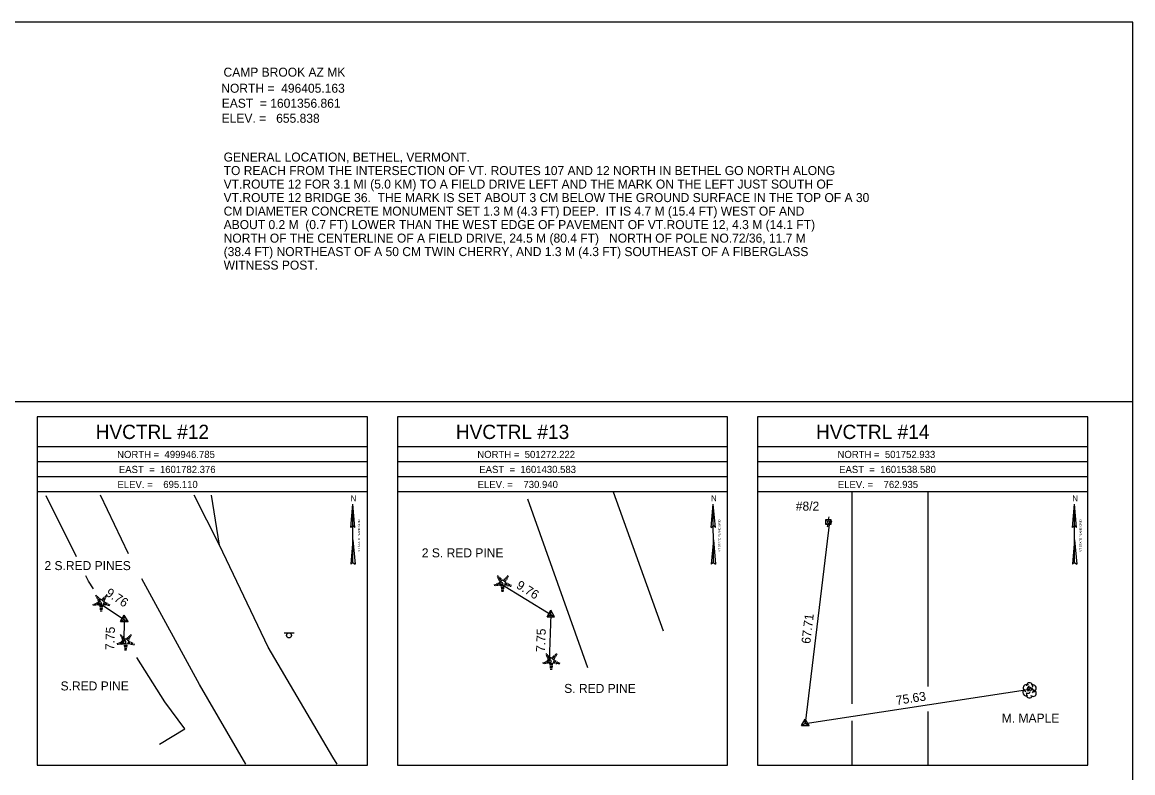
# Model space of a CAD drawing. Extents: x 1598730 to 1599370, y 501440 to 502728.
# Drawn here: x 1598999.5 to 1599369.5, y 502042.9 to 502293 of the extents above; entities that cross this region are included whole.
import ezdxf

# ---------------------------------------------------------------- set-up
doc = ezdxf.new("R2010")
doc.units = 0
for name, color, linetype in [('CBP', 7, 'Continuous'), ('CPSM', 7, 'Continuous'), ('Default', 7, 'Continuous'), ('L_C', 7, 'Continuous'), ('LAWA', 7, 'Continuous'), ('LTC', 7, 'Continuous'), ('LTD', 7, 'Continuous'), ('NBL1', 7, 'Continuous'), ('NBL2', 7, 'Continuous'), ('NNA_P', 7, 'Continuous'), ('PET', 7, 'Continuous'), ('RDG', 7, 'Continuous'), ('SSGN', 7, 'Continuous'), ('U_C', 7, 'Continuous'), ('UP', 7, 'Continuous')]:
    doc.layers.add(name, color=color, linetype=linetype)

msp = doc.modelspace()

# ---------------------------------------------------------------- linework, layer by layer
at = {"layer": 'CBP'}
for centre, radius in [((1599268.48, 502126.59), 0.625), ((1599268.48, 502126.59), 0.0833), ((1599159.02, 502105.88), 0.625), ((1599159.02, 502105.88), 0.0833), ((1599025.29, 502099.39), 0.625), ((1599025.29, 502099.39), 0.0833), ((1599033.34, 502086.52), 0.625), ((1599033.34, 502086.52), 0.0833), ((1599175.12, 502080.15), 0.625), ((1599175.12, 502080.15), 0.0833), ((1599335.18, 502070.79), 0.625), ((1599335.18, 502070.79), 0.0833)]:
    msp.add_circle(centre, radius, dxfattribs=at)
at = {"layer": 'CPSM'}
for p, q in [((1599032.29, 502093.33), (1599033.54, 502095.5)), ((1599034.79, 502093.33), (1599033.54, 502095.5)), ((1599033.54, 502094.05), (1599033.54, 502095.5)), ((1599174.39, 502094.93), (1599175.64, 502097.1)), ((1599174.39, 502094.93), (1599175.64, 502095.65)), ((1599174.39, 502094.93), (1599176.89, 502094.93)), ((1599176.89, 502094.93), (1599175.64, 502097.1)), ((1599175.64, 502095.65), (1599175.64, 502097.1)), ((1599175.64, 502095.65), (1599175.64, 502095.65)), ((1599175.64, 502095.65), (1599176.89, 502094.93)), ((1599032.29, 502093.33), (1599033.54, 502094.05)), ((1599032.29, 502093.33), (1599034.79, 502093.33)), ((1599033.54, 502094.05), (1599033.54, 502094.05)), ((1599033.54, 502094.05), (1599034.79, 502093.33)), ((1599259.18, 502058.64), (1599260.43, 502060.8)), ((1599259.18, 502058.64), (1599260.43, 502059.36)), ((1599259.18, 502058.64), (1599261.68, 502058.64)), ((1599261.68, 502058.64), (1599260.43, 502060.8)), ((1599260.43, 502059.36), (1599260.43, 502060.8)), ((1599260.43, 502059.36), (1599260.43, 502059.36)), ((1599260.43, 502059.36), (1599261.68, 502058.64))]:
    msp.add_line(p, q, dxfattribs=at)
at = {"layer": 'Default'}
for p, q in [((1599268.48, 502126.59), (1599260.43, 502059.36)), ((1599159.02, 502105.88), (1599175.64, 502095.65)), ((1599025.29, 502099.39), (1599033.54, 502094.05)), ((1599175.64, 502095.65), (1599175.12, 502080.15)), ((1599033.54, 502094.05), (1599033.34, 502086.52)), ((1599260.43, 502059.36), (1599335.18, 502070.79))]:
    msp.add_line(p, q, dxfattribs=at)
at = {"layer": 'LAWA'}
for points in [[(1599017.62, 502114.88), (1599007.56, 502135.25)], [(1599023.27, 502104.18), (1599021.6, 502106.82), (1599020.73, 502108.58)], [(1599045.31, 502052.43), (1599053.66, 502057.56), (1599047.04, 502066.58), (1599037.69, 502081.36)]]:
    msp.add_lwpolyline(points, dxfattribs=at)
at = {"layer": 'LTC'}
for p, q in [((1599156.75, 502105.65), (1599156.9, 502105.18)), ((1599157.21, 502105.87), (1599157.42, 502105.22)), ((1599157.66, 502106.08), (1599157.93, 502105.25)), ((1599157.72, 502108.37), (1599158.07, 502108.63)), ((1599157.93, 502107.91), (1599158.46, 502108.29)), ((1599158.12, 502106.3), (1599158.45, 502105.28)), ((1599158.14, 502107.44), (1599158.84, 502107.95)), ((1599158.35, 502106.97), (1599159.23, 502107.61)), ((1599158.57, 502106.52), (1599159.58, 502107.25)), ((1599158.57, 502106.52), (1599158.96, 502105.33)), ((1599159.58, 502107.25), (1599160.58, 502106.53)), ((1599160, 502107.57), (1599160.81, 502106.98)), ((1599160.58, 502106.53), (1599160.19, 502105.33)), ((1599160.38, 502107.91), (1599161.05, 502107.42)), ((1599161.02, 502106.26), (1599160.68, 502105.22)), ((1599160.75, 502108.26), (1599161.3, 502107.86)), ((1599161.12, 502108.61), (1599161.54, 502108.31)), ((1599161.46, 502106.01), (1599161.18, 502105.12)), ((1599161.91, 502105.76), (1599161.67, 502105.03)), ((1599162.35, 502105.51), (1599162.17, 502104.93)), ((1599023.99, 502101.88), (1599024.34, 502102.13)), ((1599024.2, 502101.41), (1599024.73, 502101.8)), ((1599027.02, 502101.77), (1599027.56, 502101.37)), ((1599027.39, 502102.12), (1599027.81, 502101.81)), ((1599160.19, 502105.33), (1599158.96, 502105.33)), ((1599160.15, 502104.83), (1599159.01, 502104.83)), ((1599160.07, 502104.33), (1599159.08, 502104.33)), ((1599159.98, 502103.83), (1599159.15, 502103.83)), ((1599159.9, 502103.33), (1599159.23, 502103.33)), ((1599023.02, 502099.16), (1599023.17, 502098.69)), ((1599023.48, 502099.37), (1599023.69, 502098.72)), ((1599023.93, 502099.59), (1599024.2, 502098.75)), ((1599024.39, 502099.81), (1599024.72, 502098.79)), ((1599024.41, 502100.95), (1599025.11, 502101.46)), ((1599024.62, 502100.48), (1599025.5, 502101.12)), ((1599024.84, 502100.03), (1599025.85, 502100.76)), ((1599024.84, 502100.03), (1599025.23, 502098.83)), ((1599026.46, 502098.83), (1599025.23, 502098.83)), ((1599026.42, 502098.33), (1599025.28, 502098.33)), ((1599025.85, 502100.76), (1599026.85, 502100.03)), ((1599026.27, 502101.07), (1599027.08, 502100.48)), ((1599026.85, 502100.03), (1599026.46, 502098.83)), ((1599026.64, 502101.42), (1599027.32, 502100.93)), ((1599027.29, 502099.76), (1599026.95, 502098.72)), ((1599027.73, 502099.51), (1599027.44, 502098.63)), ((1599028.18, 502099.26), (1599027.94, 502098.53)), ((1599028.62, 502099.01), (1599028.43, 502098.44)), ((1599026.34, 502097.83), (1599025.35, 502097.83)), ((1599026.25, 502097.33), (1599025.42, 502097.33)), ((1599026.17, 502096.83), (1599025.49, 502096.83)), ((1599032.14, 502088.79), (1599032.5, 502089.05)), ((1599032.35, 502088.33), (1599032.88, 502088.71)), ((1599032.56, 502087.86), (1599033.27, 502088.37)), ((1599032.77, 502087.4), (1599033.65, 502088.03)), ((1599033, 502086.94), (1599034.01, 502087.68)), ((1599033, 502086.94), (1599033.39, 502085.75)), ((1599034.01, 502087.68), (1599035.01, 502086.95)), ((1599034.43, 502087.99), (1599035.24, 502087.4)), ((1599035.01, 502086.95), (1599034.62, 502085.75)), ((1599034.8, 502088.34), (1599035.48, 502087.84)), ((1599035.17, 502088.69), (1599035.72, 502088.29)), ((1599035.54, 502089.03), (1599035.96, 502088.73)), ((1599031.18, 502086.07), (1599031.33, 502085.6)), ((1599031.63, 502086.29), (1599031.84, 502085.64)), ((1599032.09, 502086.51), (1599032.36, 502085.67)), ((1599032.54, 502086.72), (1599032.87, 502085.7)), ((1599034.62, 502085.75), (1599033.39, 502085.75)), ((1599034.58, 502085.25), (1599033.43, 502085.25)), ((1599034.49, 502084.75), (1599033.51, 502084.75)), ((1599034.41, 502084.25), (1599033.58, 502084.25)), ((1599034.33, 502083.75), (1599033.65, 502083.75)), ((1599035.44, 502086.68), (1599035.11, 502085.64)), ((1599035.89, 502086.43), (1599035.6, 502085.54)), ((1599036.33, 502086.18), (1599036.1, 502085.45)), ((1599036.78, 502085.93), (1599036.59, 502085.35)), ((1599172.96, 502079.7), (1599173.11, 502079.23)), ((1599173.41, 502079.92), (1599173.63, 502079.26)), ((1599173.87, 502080.13), (1599174.14, 502079.3)), ((1599173.93, 502082.42), (1599174.28, 502082.68)), ((1599174.14, 502081.95), (1599174.67, 502082.34)), ((1599174.33, 502080.35), (1599174.66, 502079.33)), ((1599174.35, 502081.49), (1599175.05, 502082)), ((1599174.56, 502081.02), (1599175.43, 502081.66)), ((1599174.78, 502080.57), (1599175.79, 502081.3)), ((1599174.78, 502080.57), (1599175.17, 502079.37)), ((1599175.79, 502081.3), (1599176.79, 502080.58)), ((1599176.21, 502081.62), (1599177.02, 502081.03)), ((1599176.79, 502080.58), (1599176.4, 502079.37)), ((1599176.58, 502081.96), (1599177.26, 502081.47)), ((1599177.23, 502080.31), (1599176.89, 502079.27)), ((1599176.95, 502082.31), (1599177.5, 502081.91)), ((1599177.32, 502082.66), (1599177.74, 502082.36)), ((1599177.67, 502080.06), (1599177.38, 502079.17)), ((1599178.12, 502079.81), (1599177.88, 502079.08)), ((1599178.56, 502079.56), (1599178.37, 502078.98)), ((1599176.4, 502079.37), (1599175.17, 502079.37)), ((1599176.36, 502078.87), (1599175.21, 502078.87)), ((1599176.28, 502078.37), (1599175.29, 502078.37)), ((1599176.19, 502077.87), (1599175.36, 502077.87)), ((1599176.11, 502077.37), (1599175.43, 502077.37))]:
    msp.add_line(p, q, dxfattribs=at)
at = {"layer": 'LTD'}
msp.add_line((1599335.12, 502070.44), (1599335.12, 502070.44), dxfattribs=at)
msp.add_line((1599335.12, 502070.44), (1599335.12, 502070.44), dxfattribs=at)
msp.add_arc((1599335.17, 502071.88), 1.05, 335.5272, 180.9563, dxfattribs=at)
for centre, major_axis, ratio, start_param, end_param in [((1599334.33, 502071.11), (1.21, -0.51), 0.895232, 1.570796, 4.712389), ((1599336.16, 502071.03), (-1.14, -0.48), 0.949671, 1.570796, 4.712389), ((1599334.04, 502069.74), (0.58, -1.04), 0.959034, 3.141593, 6.283185), ((1599335.12, 502068.94), (0.26, 1.06), 0.942809, 1.570796, 4.712389), ((1599334.66, 502069.69), (-0.625, -0.083), 0.423636, 0, 3.141593), ((1599334.91, 502070.9), (-0.208, -0.792), 0.645439, 3.141593, 6.283185), ((1599335.62, 502070.28), (-0.5, 0.667), 0.989748, 3.141593, 6.283185), ((1599336.12, 502069.61), (-1.09, 0.79), 0.841452, 1.570796, 4.712389)]:
    msp.add_ellipse(centre, major_axis=major_axis, ratio=ratio, start_param=start_param, end_param=end_param, dxfattribs=at)
at = {"layer": 'NBL1'}
msp.add_lwpolyline([(1598729.53, 501873.01), (1599369.53, 501873.01), (1599369.53, 502293.01), (1598729.53, 502293.01)], close=True, dxfattribs=at)
at = {"layer": 'NBL2'}
for p, q in [((1598729.53, 502166.68), (1599369.53, 502166.68)), ((1599114.53, 502151.51), (1599004.53, 502151.51)), ((1599234.53, 502151.51), (1599124.53, 502151.51)), ((1599354.53, 502151.51), (1599244.53, 502151.51)), ((1599114.53, 502146.51), (1599004.53, 502146.51)), ((1599234.53, 502146.51), (1599124.53, 502146.51)), ((1599354.53, 502146.51), (1599244.53, 502146.51)), ((1599114.53, 502141.51), (1599004.53, 502141.51)), ((1599234.53, 502141.51), (1599124.53, 502141.51)), ((1599354.53, 502141.51), (1599244.53, 502141.51)), ((1599114.53, 502136.51), (1599004.53, 502136.51)), ((1599234.53, 502136.51), (1599124.53, 502136.51)), ((1599354.53, 502136.51), (1599244.53, 502136.51))]:
    msp.add_line(p, q, dxfattribs=at)
for points in [[(1599004.53, 502045.51), (1599114.53, 502045.51), (1599114.53, 502161.51), (1599004.53, 502161.51)], [(1599124.53, 502045.51), (1599234.53, 502045.51), (1599234.53, 502161.51), (1599124.53, 502161.51)], [(1599244.53, 502045.51), (1599354.53, 502045.51), (1599354.53, 502161.51), (1599244.53, 502161.51)]]:
    msp.add_lwpolyline(points, close=True, dxfattribs=at)
at = {"layer": 'NNA_P'}
for p, q in [((1599109.01, 502124.61), (1599109.7, 502132.4)), ((1599109.71, 502113.03), (1599109.7, 502132.4)), ((1599110.4, 502124.61), (1599109.7, 502132.4)), ((1599229.09, 502124.61), (1599229.78, 502132.4)), ((1599229.79, 502113.03), (1599229.78, 502132.4)), ((1599230.48, 502124.61), (1599229.78, 502132.4)), ((1599349.43, 502124.61), (1599350.12, 502132.4)), ((1599350.13, 502113.03), (1599350.12, 502132.4)), ((1599350.82, 502124.61), (1599350.12, 502132.4)), ((1599109.01, 502124.61), (1599109.7, 502125.37)), ((1599110.4, 502124.61), (1599109.71, 502125.37)), ((1599229.09, 502124.61), (1599229.79, 502125.37)), ((1599230.48, 502124.61), (1599229.79, 502125.37)), ((1599349.43, 502124.61), (1599350.12, 502125.37)), ((1599350.82, 502124.61), (1599350.13, 502125.37)), ((1599109.71, 502120.55), (1599108.99, 502112.39)), ((1599109.71, 502120.55), (1599110.43, 502112.39)), ((1599229.79, 502120.55), (1599229.07, 502112.39)), ((1599229.79, 502120.55), (1599230.51, 502112.39)), ((1599350.13, 502120.55), (1599349.41, 502112.39)), ((1599350.13, 502120.55), (1599350.85, 502112.39)), ((1599109.71, 502113.03), (1599108.99, 502112.39)), ((1599109.71, 502113.03), (1599110.43, 502112.39)), ((1599229.79, 502113.03), (1599229.07, 502112.39)), ((1599229.79, 502113.03), (1599230.51, 502112.39)), ((1599350.13, 502113.03), (1599349.41, 502112.39)), ((1599350.13, 502113.03), (1599350.85, 502112.39))]:
    msp.add_line(p, q, dxfattribs=at)
at = {"layer": 'PET'}
for points in [[(1599034.98, 502115.83), (1599025.58, 502135.48)], [(1599104.48, 502045.81), (1599103.01, 502048.17), (1599081.45, 502084.79), (1599065.29, 502118.75), (1599056.78, 502135.48)], [(1599196.43, 502136.51), (1599213.07, 502090.21)], [(1599275.89, 502136.51), (1599275.89, 502065.89)], [(1599301.25, 502136.51), (1599301.25, 502071.71)], [(1599167.83, 502134.25), (1599187.82, 502077.96)], [(1599074.08, 502045.81), (1599058.64, 502072.38), (1599039.39, 502107.58)], [(1599301.25, 502063.3), (1599301.25, 502045.51)], [(1599275.89, 502060.22), (1599275.89, 502045.51)]]:
    msp.add_lwpolyline(points, dxfattribs=at)
at = {"layer": 'RDG'}
msp.add_lwpolyline([(1599065.29, 502118.75), (1599062.55, 502135.48)], dxfattribs=at)
at = {"layer": 'SSGN'}
for p, q in [((1599086.77, 502089.54), (1599090.11, 502089.54)), ((1599088.42, 502088.71), (1599088.42, 502088.71))]:
    msp.add_line(p, q, dxfattribs=at)
msp.add_circle((1599088.42, 502088.71), 0.833, dxfattribs=at)
at = {"layer": 'UP'}
for p, q in [((1599268.32, 502128.18), (1599268.07, 502127.34)), ((1599267.23, 502125.68), (1599267.23, 502127.34)), ((1599267.23, 502127.34), (1599268.9, 502127.34)), ((1599268.9, 502125.68), (1599267.23, 502125.68)), ((1599267.82, 502124.84), (1599268.07, 502125.68)), ((1599268.07, 502126.51), (1599268.07, 502126.51)), ((1599268.9, 502127.34), (1599268.9, 502125.68))]:
    msp.add_line(p, q, dxfattribs=at)
msp.add_circle((1599268.07, 502126.51), 0.833, dxfattribs=at)

# ---------------------------------------------------------------- texts
at = {"layer": 'Default'}
for s, p in [('GENERAL LOCATION, BETHEL, VERMONT.  ', (1599066.65, 502246.58)), ('TO REACH FROM THE INTERSECTION OF VT. ROUTES 107 AND 12 NORTH IN BETHEL GO NORTH ALONG ', (1599066.65, 502242.08)), ('VT.ROUTE 12 FOR 3.1 MI (5.0 KM) TO A FIELD DRIVE LEFT AND THE MARK ON THE LEFT JUST SOUTH OF ', (1599066.65, 502237.58)), ('VT.ROUTE 12 BRIDGE 36.  THE MARK IS SET ABOUT 3 CM BELOW THE GROUND SURFACE IN THE TOP OF A 30 ', (1599066.65, 502233.08)), ('CM DIAMETER CONCRETE MONUMENT SET 1.3 M (4.3 FT) DEEP.  IT IS 4.7 M (15.4 FT) WEST OF AND ', (1599066.65, 502228.58)), ('ABOUT 0.2 M  (0.7 FT) LOWER THAN THE WEST EDGE OF PAVEMENT OF VT.ROUTE 12, 4.3 M (14.1 FT) ', (1599066.65, 502224.08)), ('NORTH OF THE CENTERLINE OF A FIELD DRIVE, 24.5 M (80.4 FT)   NORTH OF POLE NO.72/36, 11.7 M ', (1599066.65, 502219.58)), ('(38.4 FT) NORTHEAST OF A 50 CM TWIN CHERRY, AND 1.3 M (4.3 FT) SOUTHEAST OF A FIBERGLASS ', (1599066.65, 502215.08)), ('WITNESS POST. ', (1599066.65, 502210.58))]:
    msp.add_text(s, height=3, dxfattribs=at).set_placement(p)
for s, rotation, p in [('9.76', 328.3986, (1599163.86, 502104.66)), ('9.76', 327.1143, (1599027.07, 502102.17)), ('67.71', 83.1662, (1599262.08, 502085.79)), ('7.75', 88.4587, (1599030.22, 502083.75)), ('7.75', 88.0567, (1599173.72, 502083.13)), ('75.63', 8.6972, (1599290.87, 502065.53))]:
    msp.add_text(s, height=3, rotation=rotation, dxfattribs=at).set_placement(p)
at = {"layer": 'L_C'}
for s, p in [('2 S. RED PINE', (1599132.67, 502114.71)), ('2 S.RED PINES', (1599006.94, 502110.46)), ('S.RED PINE', (1599012.32, 502070.37)), ('S. RED PINE', (1599180.1, 502069.54)), ('M. MAPLE', (1599325.88, 502059.64))]:
    msp.add_text(s, height=3, dxfattribs=at).set_placement(p)
at = {"layer": 'LTC'}
for p in [(1599159.47, 502106.27), (1599025.74, 502099.77), (1599033.89, 502086.69), (1599175.67, 502080.32)]:
    msp.add_text('.', height=1.04, rotation=270, dxfattribs=at).set_placement(p)
at = {"layer": 'NBL2'}
for s, height, p in [('  CAMP BROOK AZ MK   ', 3, (1599064.37, 502274.87)), ('NORTH =  496405.163 ', 3, (1599065.86, 502269.51)), ('EAST  = 1601356.861 ', 3, (1599066.01, 502264.51)), ('ELEV. =   655.838   ', 3, (1599065.97, 502259.51)), ('     HVCTRL #12    ', 4.75, (1599015.18, 502154.14)), ('     HVCTRL #13    ', 4.75, (1599135.18, 502154.14)), ('     HVCTRL #14    ', 4.75, (1599255.18, 502154.14)), ('NORTH =  499946.785 ', 2.375, (1599031.15, 502147.82)), ('NORTH =  501272.222 ', 2.375, (1599151.15, 502147.82)), ('NORTH =  501752.933 ', 2.375, (1599271.15, 502147.82)), ('EAST  =  1601782.376', 2.375, (1599031.74, 502142.82)), ('EAST  =  1601430.583', 2.375, (1599151.81, 502142.82)), ('EAST  =  1601538.580', 2.375, (1599271.71, 502142.82)), ('ELEV. =    695.110  ', 2.375, (1599031.26, 502137.82)), ('ELEV. =    730.940  ', 2.375, (1599151.26, 502137.82)), ('ELEV. =    762.935  ', 2.375, (1599271.26, 502137.82))]:
    msp.add_text(s, height=height, dxfattribs=at).set_placement(p)
at = {"layer": 'NNA_P'}
for p in [(1599108.94, 502133.41), (1599229.02, 502133.41), (1599349.36, 502133.41)]:
    msp.add_text('N', height=1.97, dxfattribs=at).set_placement(p)
for p in [(1599112.06, 502116.59), (1599232.14, 502116.59), (1599352.48, 502116.59)]:
    msp.add_text('VT STATE PLANE GRID', height=0.7, rotation=90.0204, dxfattribs=at).set_placement(p)
at = {"layer": 'U_C'}
msp.add_text('#8/2', height=3, dxfattribs=at).set_placement((1599257.26, 502130.27))

doc.saveas('drawing.dxf')
